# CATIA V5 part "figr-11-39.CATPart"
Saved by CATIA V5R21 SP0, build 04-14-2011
Part number: Part1
Bounding box of the stored display mesh (mm): x -177 to 59, y -180 to 60, z 0 to 80
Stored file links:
  D:\CATIA V5R21 E-RESOURCES\CATIA-V5R21\catia-v5r21-prt\c11-catia-v5r21-prt\c11-catia-v5r21-figr-11-39.CATPart
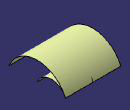
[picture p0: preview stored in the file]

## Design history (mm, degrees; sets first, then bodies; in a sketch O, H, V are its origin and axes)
Set1
  Extrude1: Element1 Sketch1, Lim1 59, Lim2 59, Direction yz-plane
  Scaling1: ToTransfor Extrude1, Reference vertex [face of Extrude1], Ratio 2
Body1 (main body)
  Sketch1 on yz-plane, origin (0, 0, 0), H (0, 1, 0), V (0, 0, 1)
    arc A1 centre (0, -25) radius 65 from (-60, 0) to (60, 0) cw
    point P2 (-60, 0)
    point P3 (60, 0)
    coincidence: P2 H, P3 H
